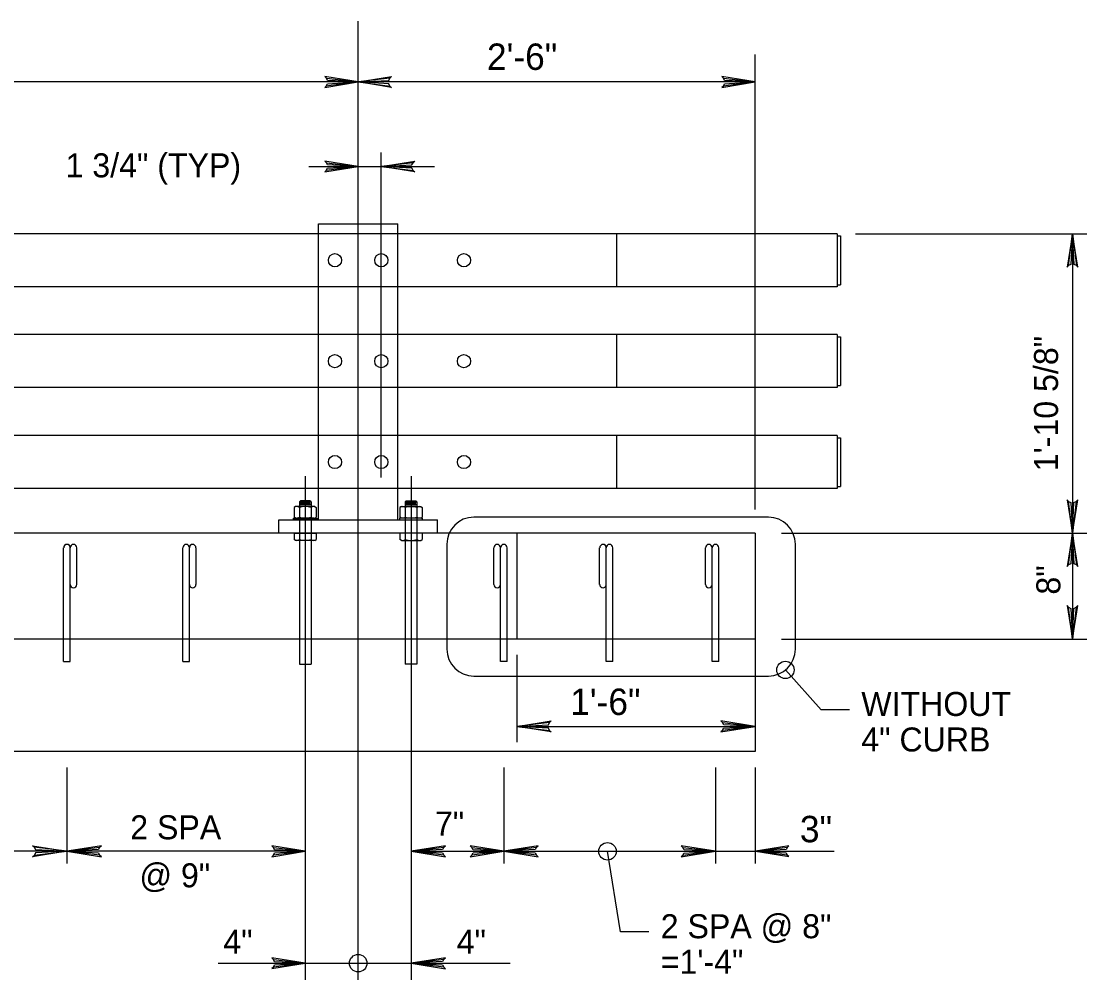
# Model space of a CAD drawing. Extents: x 641054 to 641910, y 298137 to 299325.
# Drawn here: x 641533.3 to 641666.4, y 299066.5 to 299186.2 of the extents above; entities that cross this region are included whole.
import ezdxf

# ---------------------------------------------------------------- set-up
doc = ezdxf.new("R2010")
doc.units = 0
for name, color, linetype in [('1', 7, 'Continuous'), ('2', 7, 'Continuous'), ('Default', 7, 'Continuous')]:
    doc.layers.add(name, color=color, linetype=linetype)

msp = doc.modelspace()

# ---------------------------------------------------------------- linework, layer by layer
at = {"layer": '1'}
for p, q in [((641568.07, 299126.17), (641568.19, 299126.29)), ((641568.07, 299126.17), (641568.07, 299125.57)), ((641569.52, 299126.17), (641568.07, 299126.17)), ((641569.52, 299125.81), (641568.07, 299125.81)), ((641568.07, 299125.77), (641568.07, 299105.88)), ((641569.4, 299125.99), (641568.18, 299125.99)), ((641569.4, 299125.63), (641568.18, 299125.63)), ((641569.39, 299126.29), (641568.19, 299126.29)), ((641569.52, 299126.17), (641569.39, 299126.29)), ((641569.52, 299126.17), (641569.52, 299125.57)), ((641569.52, 299125.77), (641569.52, 299105.88)), ((641581.29, 299126.17), (641581.42, 299126.29)), ((641581.29, 299126.17), (641581.29, 299125.57)), ((641581.29, 299126.17), (641582.74, 299126.17)), ((641581.29, 299125.81), (641582.74, 299125.81)), ((641581.29, 299125.77), (641581.29, 299105.88)), ((641581.41, 299125.99), (641582.63, 299125.99)), ((641581.41, 299125.63), (641582.63, 299125.63)), ((641581.42, 299126.29), (641582.62, 299126.29)), ((641582.74, 299126.17), (641582.62, 299126.29)), ((641582.74, 299126.17), (641582.74, 299125.57)), ((641582.74, 299125.77), (641582.74, 299105.88)), ((641567.59, 299125.57), (641567.4, 299125.46)), ((641567.4, 299125.46), (641567.4, 299124.25)), ((641570, 299125.57), (641567.59, 299125.57)), ((641568.07, 299125.46), (641568.07, 299124.25)), ((641569.52, 299125.46), (641569.52, 299124.25)), ((641570, 299125.57), (641570.18, 299125.46)), ((641570.18, 299125.46), (641570.18, 299124.25)), ((641580.81, 299125.57), (641580.63, 299125.46)), ((641580.63, 299125.46), (641580.63, 299124.25)), ((641580.81, 299125.57), (641583.22, 299125.57)), ((641581.29, 299125.46), (641581.29, 299124.25)), ((641582.74, 299125.46), (641582.74, 299124.25)), ((641583.22, 299125.57), (641583.41, 299125.46)), ((641583.41, 299125.46), (641583.41, 299124.25)), ((641567.59, 299124.14), (641567.4, 299124.25)), ((641570, 299124.14), (641570.18, 299124.25)), ((641580.81, 299124.14), (641580.63, 299124.25)), ((641583.22, 299124.14), (641583.41, 299124.25)), ((641567.4, 299122.24), (641567.4, 299121.45)), ((641567.4, 299122.24), (641570.18, 299122.24)), ((641568.07, 299122.24), (641568.07, 299121.45)), ((641569.52, 299122.24), (641569.52, 299121.45)), ((641570.18, 299122.24), (641570.18, 299121.45)), ((641580.63, 299122.24), (641580.63, 299121.45)), ((641583.41, 299122.24), (641580.63, 299122.24)), ((641581.29, 299122.24), (641581.29, 299121.45)), ((641582.74, 299122.24), (641582.74, 299121.45)), ((641583.41, 299122.24), (641583.41, 299121.45)), ((641567.59, 299121.34), (641567.4, 299121.45)), ((641570, 299121.34), (641567.59, 299121.34)), ((641570, 299121.34), (641570.18, 299121.45)), ((641580.81, 299121.34), (641580.63, 299121.45)), ((641580.81, 299121.34), (641583.22, 299121.34)), ((641583.22, 299121.34), (641583.41, 299121.45)), ((641568.07, 299105.88), (641569.52, 299105.88)), ((641582.74, 299105.88), (641581.29, 299105.88))]:
    msp.add_line(p, q, dxfattribs=at)
for points in [[(641567.35, 299123.9), (641567.35, 299124.14), (641570.24, 299124.14), (641570.24, 299123.9)], [(641583.46, 299123.9), (641583.46, 299124.14), (641580.57, 299124.14), (641580.57, 299123.9)]]:
    msp.add_lwpolyline(points, close=True, dxfattribs=at)
for points in [[(641599.33, 299097.6), (641599.18, 299097.9), (641595.25, 299098.11), (641599.33, 299097.6), (641599.54, 299097.42), (641595.25, 299098.11), (641599.18, 299098.31), (641599.32, 299098.6), (641595.25, 299098.11), (641599.54, 299098.8), (641599.32, 299098.6)], [(641620.92, 299097.6), (641621.07, 299097.9), (641625.01, 299098.11), (641620.92, 299097.6), (641620.71, 299097.42), (641625.01, 299098.11), (641621.08, 299098.31), (641620.93, 299098.6), (641625.01, 299098.11), (641620.71, 299098.8), (641620.93, 299098.6)], [(641534.94, 299083.01), (641535.09, 299082.72), (641539.03, 299082.5), (641534.94, 299083.01), (641534.73, 299083.19), (641539.03, 299082.5), (641535.1, 299082.31), (641534.95, 299082.01), (641539.03, 299082.5), (641534.73, 299081.82), (641534.95, 299082.01)], [(641543.11, 299083.01), (641542.96, 299082.72), (641539.03, 299082.5), (641543.11, 299083.01), (641543.32, 299083.19), (641539.03, 299082.5), (641542.96, 299082.31), (641543.1, 299082.01), (641539.03, 299082.5), (641543.32, 299081.82), (641543.1, 299082.01)], [(641586.11, 299083.01), (641585.96, 299082.72), (641582.02, 299082.5), (641586.11, 299083.01), (641586.32, 299083.19), (641582.02, 299082.5), (641585.95, 299082.31), (641586.1, 299082.01), (641582.02, 299082.5), (641586.32, 299081.82), (641586.1, 299082.01)], [(641597.68, 299083.01), (641597.53, 299082.72), (641593.6, 299082.5), (641597.68, 299083.01), (641597.89, 299083.19), (641593.6, 299082.5), (641597.53, 299082.31), (641597.67, 299082.01), (641593.6, 299082.5), (641597.89, 299081.82), (641597.67, 299082.01)], [(641615.96, 299081.99), (641616.11, 299082.28), (641620.05, 299082.5), (641615.96, 299081.99), (641615.75, 299081.81), (641620.05, 299082.5), (641616.12, 299082.7), (641615.97, 299082.99), (641620.05, 299082.5), (641615.75, 299083.18), (641615.97, 299082.99)], [(641586.11, 299069.03), (641585.96, 299068.73), (641582.02, 299068.52), (641586.11, 299069.03), (641586.32, 299069.21), (641582.02, 299068.52), (641585.95, 299068.32), (641586.1, 299068.03), (641582.02, 299068.52), (641586.32, 299067.83), (641586.1, 299068.03)]]:
    msp.add_lwpolyline(points, dxfattribs=at)
for centre, radius, start, end in [((641567.73, 299124.99), 0.573, 54.2983, 90.0007), ((641568.79, 299123.08), 2.48, 73.0665, 106.9347), ((641569.85, 299124.99), 0.573, 90.0001, 125.7026), ((641580.96, 299124.99), 0.573, 54.2974, 89.9999), ((641582.02, 299123.08), 2.48, 73.0653, 106.9335), ((641583.08, 299124.99), 0.573, 89.9993, 125.7017), ((641567.73, 299124.72), 0.573, 270.0017, 305.7041), ((641568.79, 299126.63), 2.48, 253.0683, 286.9366), ((641569.85, 299124.72), 0.573, 234.299, 270.0015), ((641580.96, 299124.72), 0.573, 269.9985, 305.701), ((641582.02, 299126.63), 2.48, 253.0634, 286.9317), ((641583.08, 299124.72), 0.573, 234.2959, 269.9983), ((641567.73, 299121.91), 0.573, 270.0017, 305.7041), ((641568.79, 299123.82), 2.48, 253.0683, 286.9366), ((641569.85, 299121.91), 0.573, 234.299, 270.0015), ((641580.96, 299121.91), 0.573, 269.9985, 305.701), ((641582.02, 299123.82), 2.48, 253.0634, 286.9317), ((641583.08, 299121.91), 0.573, 234.2959, 269.9983)]:
    msp.add_arc(centre, radius, start, end, dxfattribs=at)
at = {"layer": '2'}
for p, q in [((641635.24, 299159.65), (641412.45, 299159.65)), ((641607.69, 299159.65), (641607.69, 299153.04)), ((641635.24, 299159.65), (641635.24, 299153.04)), ((641635.24, 299159.38), (641635.66, 299159.38)), ((641635.66, 299159.38), (641635.66, 299153.29)), ((641635.24, 299153.04), (641412.45, 299153.04)), ((641635.24, 299153.29), (641635.66, 299153.29)), ((641635.24, 299147.05), (641412.45, 299147.05)), ((641607.69, 299147.05), (641607.69, 299140.43)), ((641635.24, 299147.05), (641635.24, 299140.43)), ((641635.24, 299146.78), (641635.66, 299146.78)), ((641635.66, 299146.78), (641635.66, 299140.69)), ((641635.24, 299140.43), (641412.45, 299140.43)), ((641635.24, 299140.69), (641635.66, 299140.69)), ((641635.24, 299134.44), (641412.45, 299134.44)), ((641607.69, 299134.44), (641607.69, 299127.83)), ((641635.24, 299134.44), (641635.24, 299127.83)), ((641635.24, 299134.17), (641635.66, 299134.17)), ((641635.66, 299134.17), (641635.66, 299128.08)), ((641635.24, 299127.82), (641412.45, 299127.82)), ((641635.24, 299128.08), (641635.66, 299128.08)), ((641538.61, 299106.23), (641539.44, 299106.23)), ((641553.49, 299106.23), (641554.32, 299106.23)), ((641594.01, 299106.23), (641593.18, 299106.23)), ((641607.24, 299106.23), (641606.41, 299106.23)), ((641620.46, 299106.23), (641619.64, 299106.23))]:
    msp.add_line(p, q, dxfattribs=at)
for points in [[(641571.43, 299178.11), (641571.58, 299178.4), (641575.41, 299178.61), (641571.43, 299178.11), (641571.23, 299177.94), (641575.41, 299178.61), (641571.58, 299178.8), (641571.44, 299179.09), (641575.41, 299178.61), (641571.23, 299179.28), (641571.44, 299179.09)], [(641579.38, 299178.11), (641579.23, 299178.4), (641575.41, 299178.61), (641579.38, 299178.11), (641579.58, 299177.94), (641575.41, 299178.61), (641579.23, 299178.8), (641579.37, 299179.09), (641575.41, 299178.61), (641579.58, 299179.28), (641579.37, 299179.09)], [(641621.04, 299178.11), (641621.18, 299178.4), (641625.01, 299178.61), (641621.04, 299178.11), (641620.83, 299177.94), (641625.01, 299178.61), (641621.19, 299178.8), (641621.05, 299179.09), (641625.01, 299178.61), (641620.83, 299179.28), (641621.05, 299179.09)], [(641571.43, 299167.56), (641571.58, 299167.84), (641575.41, 299168.06), (641571.43, 299167.56), (641571.23, 299167.38), (641575.41, 299168.06), (641571.58, 299168.25), (641571.44, 299168.53), (641575.41, 299168.06), (641571.23, 299168.72), (641571.44, 299168.53)], [(641582.27, 299167.56), (641582.12, 299167.84), (641578.3, 299168.06), (641582.27, 299167.56), (641582.48, 299167.38), (641578.3, 299168.06), (641582.12, 299168.25), (641582.26, 299168.53), (641578.3, 299168.06), (641582.48, 299168.72), (641582.26, 299168.53)], [(641665.15, 299155.68), (641664.86, 299155.83), (641664.65, 299159.65), (641665.15, 299155.68), (641665.33, 299155.48), (641664.65, 299159.65), (641664.46, 299155.83), (641664.18, 299155.69), (641664.65, 299159.65), (641663.99, 299155.48), (641664.18, 299155.69)], [(641664.16, 299126.22), (641664.44, 299126.07), (641664.65, 299122.24), (641664.16, 299126.22), (641663.98, 299126.42), (641664.65, 299122.24), (641664.84, 299126.07), (641665.13, 299126.21), (641664.65, 299122.24), (641665.32, 299126.42), (641665.13, 299126.21)], [(641665.15, 299118.27), (641664.86, 299118.42), (641664.65, 299122.24), (641665.15, 299118.27), (641665.33, 299118.07), (641664.65, 299122.24), (641664.46, 299118.42), (641664.18, 299118.28), (641664.65, 299122.24), (641663.99, 299118.07), (641664.18, 299118.28)], [(641664.16, 299112.99), (641664.44, 299112.84), (641664.65, 299109.02), (641664.16, 299112.99), (641663.98, 299113.19), (641664.65, 299109.02), (641664.84, 299112.84), (641665.13, 299112.98), (641664.65, 299109.02), (641665.32, 299113.19), (641665.13, 299112.98)], [(641564.82, 299082), (641564.96, 299082.29), (641568.79, 299082.5), (641564.82, 299082), (641564.61, 299081.83), (641568.79, 299082.5), (641564.97, 299082.69), (641564.83, 299082.97), (641568.79, 299082.5), (641564.61, 299083.17), (641564.83, 299082.97)], [(641589.62, 299082), (641589.77, 299082.29), (641593.6, 299082.5), (641589.62, 299082), (641589.42, 299081.83), (641593.6, 299082.5), (641589.77, 299082.69), (641589.63, 299082.97), (641593.6, 299082.5), (641589.42, 299083.17), (641589.63, 299082.97)], [(641629.03, 299083), (641628.88, 299082.71), (641625.06, 299082.5), (641629.03, 299083), (641629.23, 299083.17), (641625.06, 299082.5), (641628.88, 299082.31), (641629.02, 299082.03), (641625.06, 299082.5), (641629.23, 299081.84), (641629.02, 299082.03)], [(641564.82, 299068.02), (641564.96, 299068.3), (641568.79, 299068.52), (641564.82, 299068.02), (641564.61, 299067.84), (641568.79, 299068.52), (641564.97, 299068.7), (641564.83, 299068.99), (641568.79, 299068.52), (641564.61, 299069.18), (641564.83, 299068.99)]]:
    msp.add_lwpolyline(points, dxfattribs=at)
for centre in [(641628.79, 299105.16), (641606.56, 299082.5), (641575.41, 299068.52)]:
    msp.add_circle(centre, 1.09, dxfattribs=at)
at = {"layer": 'Default'}
for p, q in [((641575.41, 299066.46), (641575.41, 299186.19)), ((641625.01, 299125.19), (641625.01, 299182.03)), ((641625.01, 299178.61), (641451.39, 299178.61)), ((641578.3, 299129.18), (641578.3, 299169.81)), ((641569.25, 299168.06), (641584.96, 299168.06)), ((641570.44, 299159.65), (641570.44, 299160.89)), ((641570.44, 299160.89), (641580.36, 299160.89)), ((641580.36, 299159.65), (641580.36, 299160.89)), ((641570.44, 299153.04), (641570.44, 299159.65)), ((641580.36, 299153.04), (641580.36, 299159.65)), ((641637.56, 299159.65), (641666.43, 299159.65)), ((641664.65, 299159.65), (641664.65, 299109.02)), ((641570.44, 299147.05), (641570.44, 299153.04)), ((641580.36, 299147.05), (641580.36, 299153.04)), ((641570.44, 299140.43), (641570.44, 299147.05)), ((641580.36, 299140.43), (641580.36, 299147.05)), ((641570.44, 299134.44), (641570.44, 299140.43)), ((641580.36, 299134.44), (641580.36, 299140.43)), ((641570.44, 299127.83), (641570.44, 299134.44)), ((641580.36, 299127.83), (641580.36, 299134.44)), ((641568.79, 299129.37), (641568.79, 299066.46)), ((641582.02, 299129.37), (641582.02, 299066.46)), ((641570.44, 299123.9), (641570.44, 299127.82)), ((641580.36, 299123.9), (641580.36, 299127.82)), ((641664.65, 299126.21), (641664.65, 299124.23)), ((641565.48, 299123.9), (641585.33, 299123.9)), ((641565.48, 299122.24), (641565.48, 299123.9)), ((641585.33, 299122.24), (641585.33, 299123.9)), ((641625.01, 299122.24), (641412.45, 299122.24)), ((641595.25, 299122.24), (641595.25, 299109.02)), ((641625.01, 299122.24), (641625.01, 299094.96)), ((641628.32, 299122.24), (641666.43, 299122.24)), ((641538.61, 299106.23), (641538.61, 299120.43)), ((641539.44, 299106.23), (641539.44, 299120.43)), ((641540.27, 299115.82), (641540.27, 299120.43)), ((641553.49, 299106.23), (641553.49, 299120.43)), ((641554.32, 299106.23), (641554.32, 299120.43)), ((641555.15, 299115.82), (641555.15, 299120.43)), ((641592.36, 299115.82), (641592.36, 299120.43)), ((641593.18, 299106.23), (641593.18, 299120.43)), ((641594.01, 299106.23), (641594.01, 299120.43)), ((641605.58, 299115.82), (641605.58, 299120.43)), ((641606.41, 299106.23), (641606.41, 299120.43)), ((641607.24, 299106.23), (641607.24, 299120.43)), ((641618.81, 299115.82), (641618.81, 299120.43)), ((641619.64, 299106.23), (641619.64, 299120.43)), ((641620.46, 299106.23), (641620.46, 299120.43)), ((641538.61, 299118.12), (641538.61, 299118.95)), ((641553.49, 299118.12), (641553.49, 299118.95)), ((641594.01, 299118.12), (641594.01, 299118.95)), ((641607.24, 299118.12), (641607.24, 299118.95)), ((641620.46, 299118.12), (641620.46, 299118.95)), ((641538.61, 299114.61), (641538.61, 299115.43)), ((641553.49, 299114.61), (641553.49, 299115.43)), ((641594.01, 299114.61), (641594.01, 299115.43)), ((641607.24, 299114.61), (641607.24, 299115.43)), ((641620.46, 299114.61), (641620.46, 299115.43)), ((641625.01, 299109.02), (641412.45, 299109.02)), ((641628.32, 299109.02), (641658.35, 299109.02)), ((641628.32, 299109.02), (641666.43, 299109.02)), ((641595.25, 299107.03), (641595.25, 299096.15)), ((641633.26, 299100.19), (641628.79, 299105.16)), ((641636.78, 299100.19), (641633.26, 299100.19)), ((641595.25, 299098.11), (641625.01, 299098.11)), ((641625.01, 299094.96), (641412.45, 299094.96)), ((641539.03, 299092.98), (641539.03, 299080.98)), ((641593.6, 299092.98), (641593.6, 299080.98)), ((641620.05, 299092.98), (641620.05, 299080.98)), ((641625.01, 299092.98), (641625.01, 299080.98)), ((641568.79, 299082.5), (641458.01, 299082.5)), ((641582.02, 299082.5), (641634.88, 299082.5)), ((641608.2, 299072.42), (641606.56, 299082.5)), ((641611.73, 299072.42), (641608.2, 299072.42)), ((641557.91, 299068.52), (641594.4, 299068.52))]:
    msp.add_line(p, q, dxfattribs=at)
for points in [[(641626.66, 299124.24), (641589.86, 299124.24)], [(641586.49, 299120.87), (641586.49, 299107.77)], [(641630.03, 299107.77), (641630.03, 299120.87)], [(641589.86, 299104.4), (641626.66, 299104.4)]]:
    msp.add_lwpolyline(points, dxfattribs=at)
for centre in [(641572.51, 299156.34), (641578.3, 299156.34), (641588.63, 299156.34), (641572.51, 299143.73), (641578.3, 299143.73), (641588.63, 299143.73), (641572.51, 299131.13), (641578.3, 299131.13), (641588.63, 299131.13)]:
    msp.add_circle(centre, 0.826, dxfattribs=at)
for centre, radius, start, end in [((641589.86, 299120.87), 3.37, 90, 180), ((641626.66, 299120.87), 3.37, 0, 90), ((641539.03, 299120.43), 0.413, 0, 180), ((641539.85, 299120.43), 0.413, 0, 180), ((641553.91, 299120.43), 0.413, 0, 180), ((641554.73, 299120.43), 0.413, 0, 180), ((641592.77, 299120.43), 0.413, 0, 180), ((641593.6, 299120.43), 0.413, 0, 180), ((641606, 299120.43), 0.413, 0, 180), ((641606.82, 299120.43), 0.413, 0, 180), ((641619.22, 299120.43), 0.413, 0, 180), ((641620.05, 299120.43), 0.413, 0, 180), ((641539.85, 299115.82), 0.413, 180, 0), ((641554.73, 299115.82), 0.413, 180, 0), ((641592.77, 299115.82), 0.413, 180, 0), ((641606, 299115.82), 0.413, 180, 0), ((641619.22, 299115.82), 0.413, 180, 0), ((641589.86, 299107.77), 3.37, 180, 270), ((641626.66, 299107.77), 3.37, 270, 0)]:
    msp.add_arc(centre, radius, start, end, dxfattribs=at)

# ---------------------------------------------------------------- texts
at = {"layer": '2'}
for s, height, p in [('2\'-6"', 3.3, (641591.5, 299180.12)), ('1 3/4" (TYP)', 3, (641538.85, 299166.7)), ('1\'-6"', 3.3, (641601.9, 299099.53)), ('WITHOUT', 3, (641638.27, 299099.41)), ('4" CURB', 3, (641638.27, 299094.97)), ('2 SPA', 3, (641546.93, 299084)), ('7"', 3, (641585, 299084.47)), ('3"', 3.3, (641630.6, 299083.63)), ('@ 9"', 3, (641548.08, 299078)), ('2 SPA @ 8"', 3, (641613.21, 299071.64)), ('4"', 3, (641558.56, 299069.71)), ('4"', 3, (641587.72, 299069.71)), ('=1\'-4"', 3, (641613.21, 299067.2))]:
    msp.add_text(s, height=height, dxfattribs=at).set_placement(p)
for s, p in [('1\'-10 5/8"', (641662.85, 299129.98)), ('8"', (641663.14, 299114.57))]:
    msp.add_text(s, height=3, rotation=90, dxfattribs=at).set_placement(p)

doc.saveas('drawing.dxf')
